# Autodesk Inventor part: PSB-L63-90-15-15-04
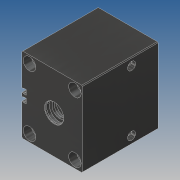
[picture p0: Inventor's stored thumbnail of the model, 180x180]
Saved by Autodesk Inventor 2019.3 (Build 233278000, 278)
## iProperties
Created: 2013-04
Part Number: PSB-L63-90-15-15-04
Material: Ogólny
Document SubType Name: Modeling
Designer: CADENGINEERING4
Density: 1 g/cm^3
Appearance: Ciemnoszara
Author: CADENGINEERING4
Revision Number: ÈÎºÎ
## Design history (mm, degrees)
feature "ÇÐ³ý-À­Éì3"
sketch "Szkic1"
  geometry: C1 r 5.25 at (9, -10) reference; C2 r 5.25 at (69, -10) reference; C3 r 5.25 at (9, -90) reference; C4 r 5.25 at (69, -90) reference; A1 r 5.25 centre (9, -10) between (9, -15.25) and (9, -4.75) reference; A2 r 5.25 centre (9, -10) between (9, -4.75) and (9, -15.25) reference; A3 r 5.25 centre (69, -10) between (69, -15.25) and (69, -4.75) reference; A4 r 5.25 centre (69, -10) between (69, -4.75) and (69, -15.25) reference; A5 r 5.25 centre (9, -90) between (9, -95.25) and (9, -84.75) reference; A6 r 5.25 centre (9, -90) between (9, -84.75) and (9, -95.25) reference; A7 r 5.25 centre (69, -90) between (69, -95.25) and (69, -84.75) reference; A8 r 5.25 centre (69, -90) between (69, -84.75) and (69, -95.25) reference; 1 further point
  node "Pętla rzutowana1"
  node "Pętla rzutowana2"
  node "Pętla rzutowana3"
  node "Pętla rzutowana4"
sketch "Szkic2"
  geometry: L1 (-1, -84.75)-(9, -84.75) reference; L2 (3.06, -84.75)-(74.67, -84.75); L3 (74.67, -84.75)-(74.67, -95.39); L4 (74.67, -95.39)-(3.06, -95.39); L5 (3.06, -95.39)-(3.06, -84.75); L6 (69, -15.25)-(79, -15.25) reference; L7 (3.06, -4.274)-(74.67, -4.274); L8 (74.67, -4.274)-(74.67, -15.25); L9 (74.67, -15.25)-(3.06, -15.25); L10 (3.06, -15.25)-(3.06, -4.274); 1 further point
  constraints: 16 end point, 4 parallel, 4 point on line, 2 horizontal, 2 perpendicular, 2 other
extrude "Wyciągnięcie proste1" join sketch "Szkic2" distance "d0" = 25; taper "d1" = 0 deg
hole "Otwór1" sketch "Szkic1" diameter "d2" = 10.106; stored, may be unused: countersink angle "d6" = 90 deg, drill point angle "d8" = 0 deg; dims "d3" = 24, "d4" = 4, "d5" = 2, "d7" = 25
node "Bryła1"
